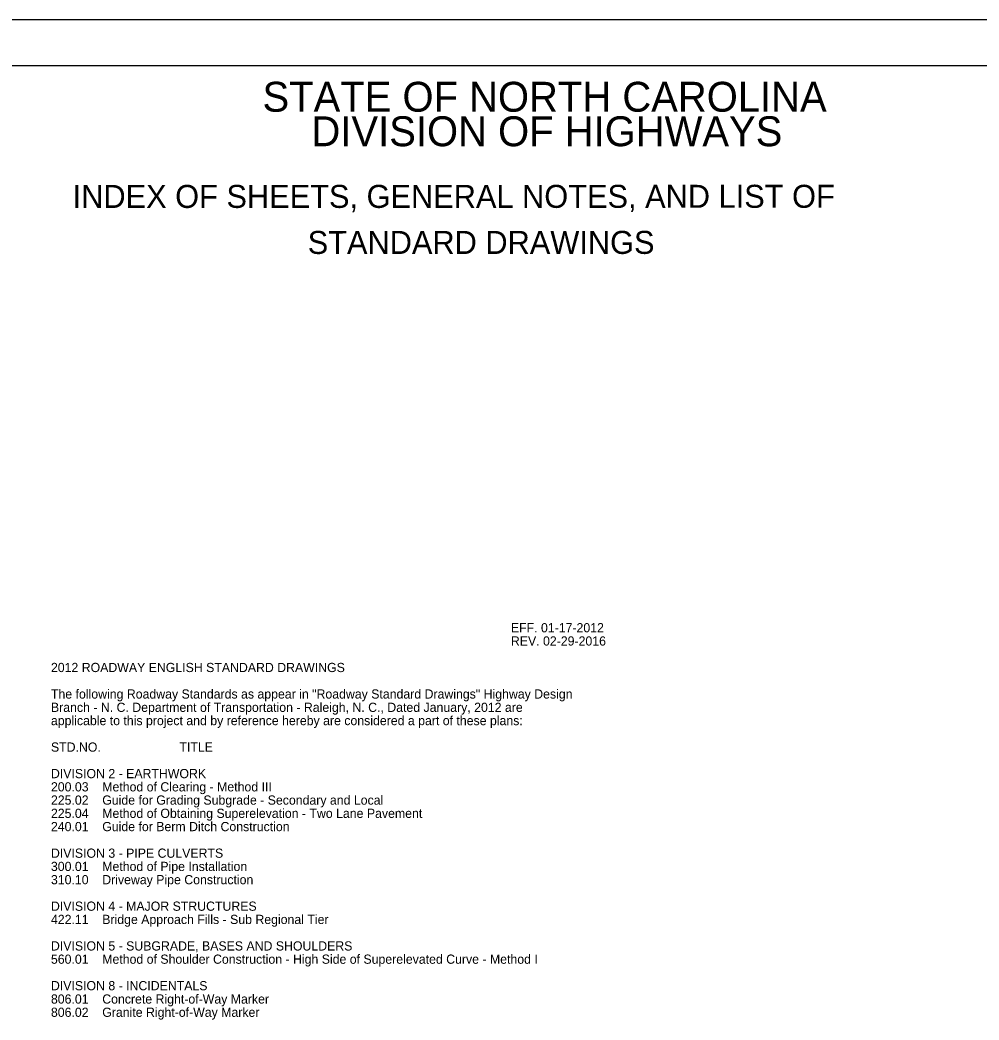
# Model space of a CAD drawing. Extents: x 972 to 1006, y 10585.8 to 10607.8.
# Drawn here: x 985.14 to 995.56, y 10596.92 to 10607.78 of the extents above; entities that cross this region are included whole.
import ezdxf

# ---------------------------------------------------------------- set-up
doc = ezdxf.new("R2010")
doc.units = 0
for name, color, linetype in [('Sheet Data Text CELL', 7, 'Continuous'), ('Sheet Plan CELL', 7, 'Continuous'), ('Sheet Summary Combination CELL', 7, 'Continuous'), ('Stewart Plot Border Xerox6279 and LJ5000', 7, 'Continuous')]:
    doc.layers.add(name, color=color, linetype=linetype)

msp = doc.modelspace()

# ---------------------------------------------------------------- linework, layer by layer
at = {"layer": 'Sheet Plan CELL'}
msp.add_lwpolyline([(1005.487, 10607.285), (975.487, 10607.285), (975.487, 10586.285), (1005.487, 10586.285)], close=True, dxfattribs=at)
at = {"layer": 'Stewart Plot Border Xerox6279 and LJ5000'}
msp.add_lwpolyline([(971.987, 10585.785), (1005.987, 10585.785), (1005.987, 10607.785), (971.987, 10607.785)], close=True, dxfattribs=at)

# ---------------------------------------------------------------- texts
at = {"layer": 'Sheet Data Text CELL'}
for s, p in [('EFF. 01-17-2012', (990.473, 10601.13)), ('REV. 02-29-2016', (990.473, 10600.986)), ('2012 ROADWAY ENGLISH STANDARD DRAWINGS', (985.473, 10600.698)), ('The following Roadway Standards as appear in "Roadway Standard Drawings" Highway Design ', (985.473, 10600.41)), ('Branch - N. C. Department of Transportation - Raleigh, N. C., Dated January, 2012 are ', (985.473, 10600.265)), ('applicable to this project and by reference hereby are considered a part of these plans:', (985.473, 10600.121)), ('STD.NO.                       TITLE', (985.473, 10599.833)), ('DIVISION 2 - EARTHWORK', (985.473, 10599.545)), ('200.03    Method of Clearing - Method III', (985.473, 10599.401)), ('225.02    Guide for Grading Subgrade - Secondary and Local', (985.473, 10599.257)), ('225.04    Method of Obtaining Superelevation - Two Lane Pavement', (985.473, 10599.113)), ('240.01    Guide for Berm Ditch Construction', (985.473, 10598.969)), ('DIVISION 3 - PIPE CULVERTS', (985.473, 10598.68)), ('300.01    Method of Pipe Installation ', (985.473, 10598.536)), ('310.10    Driveway Pipe Construction', (985.473, 10598.392)), ('DIVISION 4 - MAJOR STRUCTURES', (985.473, 10598.104)), ('422.11    Bridge Approach Fills - Sub Regional Tier', (985.473, 10597.96)), ('DIVISION 5 - SUBGRADE, BASES AND SHOULDERS', (985.473, 10597.672)), ('560.01    Method of Shoulder Construction - High Side of Superelevated Curve - Method I', (985.473, 10597.528)), ('DIVISION 8 - INCIDENTALS', (985.473, 10597.24)), ('806.01    Concrete Right-of-Way Marker', (985.473, 10597.095)), ('806.02    Granite Right-of-Way Marker', (985.473, 10596.951))]:
    msp.add_text(s, height=0.1, dxfattribs=at).set_placement(p)
at = {"layer": 'Sheet Summary Combination CELL'}
for s, p in [('STATE OF NORTH CAROLINA', (987.773, 10606.788)), ('DIVISION OF HIGHWAYS', (988.305, 10606.413))]:
    msp.add_text(s, height=0.325, dxfattribs=at).set_placement(p)
for s, p in [('INDEX OF SHEETS, GENERAL NOTES, AND LIST OF', (985.709, 10605.742)), ('STANDARD DRAWINGS', (988.264, 10605.242))]:
    msp.add_text(s, height=0.25, rotation=0.0119, dxfattribs=at).set_placement(p)

doc.saveas('drawing.dxf')
